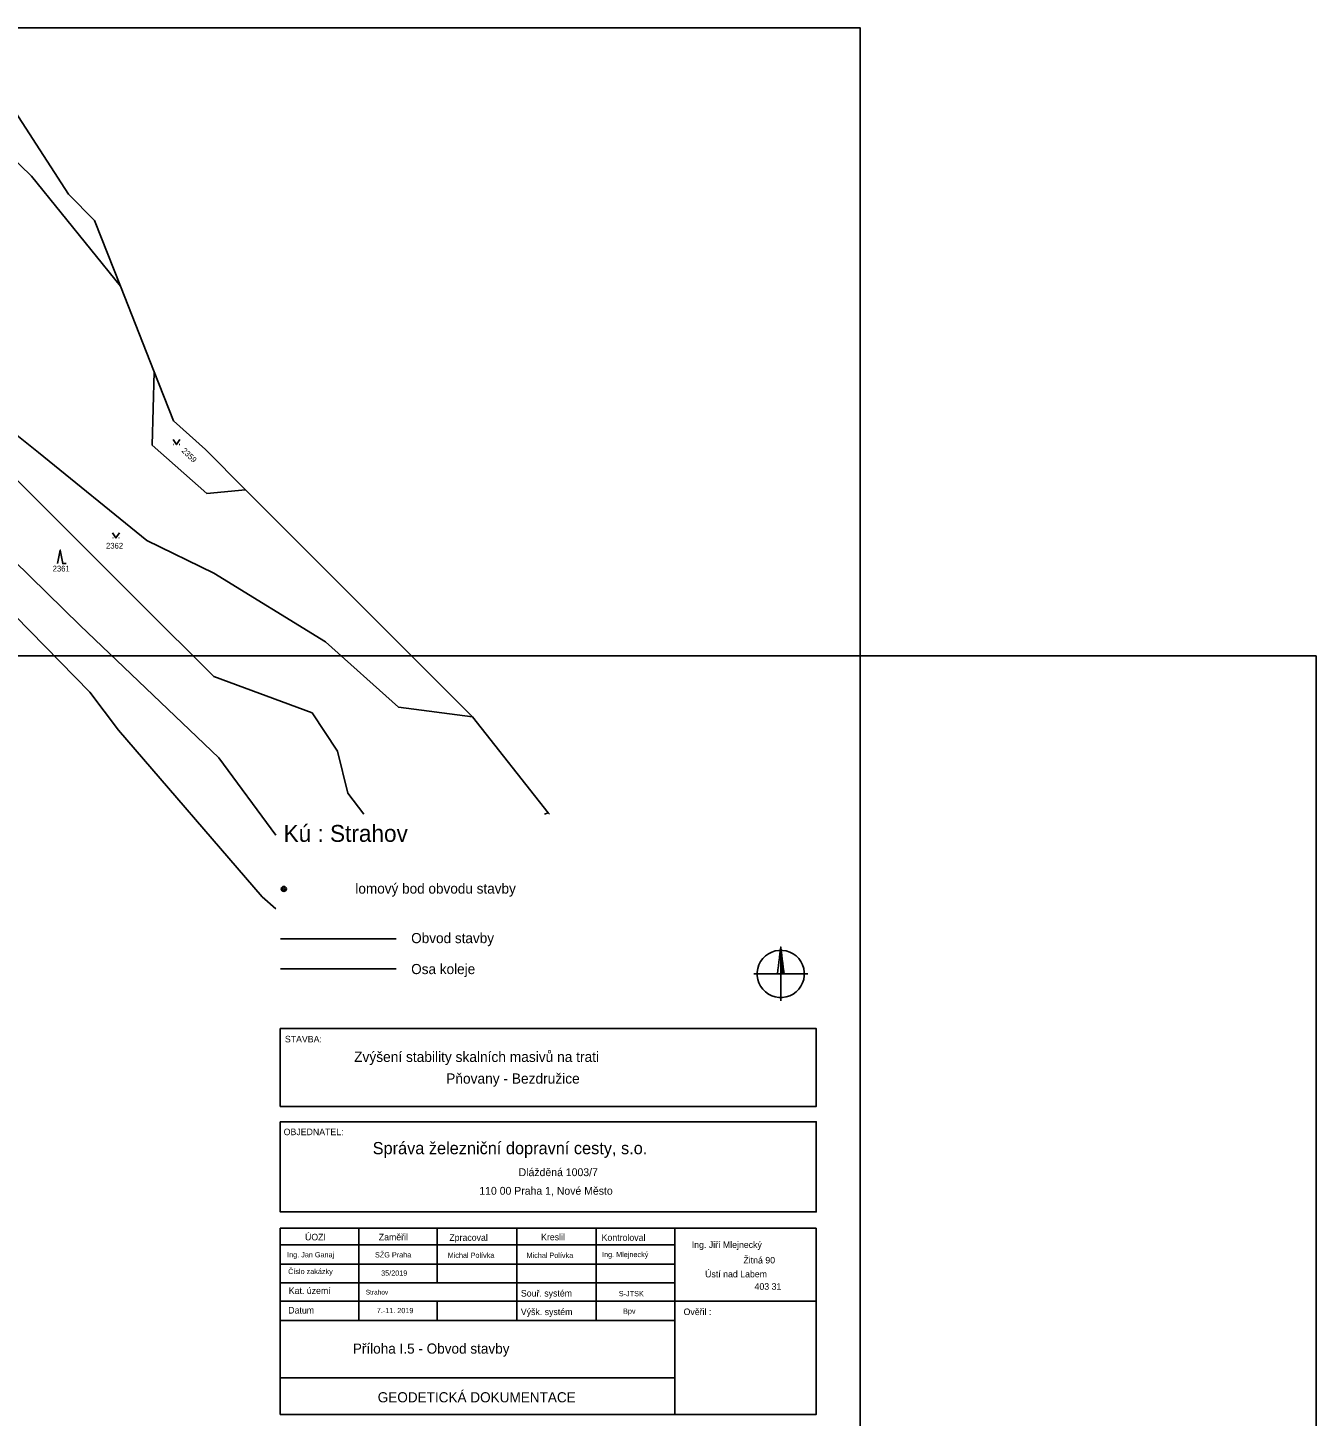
# Model space of a CAD drawing. Extents: x -852001 to -842497, y -1063614 to -1052182.
# Drawn here: x -849131.5 to -848750, y -1053225.1 to -1052814.2 of the extents above; entities that cross this region are included whole.
import ezdxf

# ---------------------------------------------------------------- set-up
doc = ezdxf.new("R2010")
doc.units = 0
for name, color, linetype in [('body', 7, 'Continuous'), ('Default', 7, 'Continuous'), ('KLADY_ZMVM', 7, 'Continuous'), ('KN_HRANICE', 7, 'Continuous'), ('KN_KULTURY', 7, 'Continuous'), ('KN_PARCELY', 7, 'Continuous'), ('LEGENDA', 7, 'Continuous'), ('tabulka', 7, 'Continuous')]:
    doc.layers.add(name, color=color, linetype=linetype)

# ---------------------------------------------------------------- blocks, each defined once
blk = doc.blocks.new('SEVER')
at = {"layer": 'Default'}
for points in [[(5.5, 69.8), (16.3, 68.1), (26.7, 64.7), (36.5, 59.7), (45.4, 53.2), (53.2, 45.4), (59.7, 36.5), (64.7, 26.7), (68.1, 16.3), (69.8, 5.5), (69.8, -5.5), (68.1, -16.3), (64.7, -26.7), (59.7, -36.5), (53.2, -45.4), (45.4, -53.2), (36.5, -59.7), (26.7, -64.7), (16.3, -68.1), (5.5, -69.8), (-5.5, -69.8), (-16.3, -68.1), (-26.7, -64.7), (-36.5, -59.7), (-45.4, -53.2), (-53.2, -45.4), (-59.7, -36.5), (-64.7, -26.7), (-68.1, -16.3), (-69.8, -5.5), (-69.8, 5.5), (-68.1, 16.3), (-64.7, 26.7), (-59.7, 36.5), (-53.2, 45.4), (-45.4, 53.2), (-36.5, 59.7), (-26.7, 64.7), (-16.3, 68.1), (-5.5, 69.8), (5.5, 69.8)], [(-10, 0), (-8.5, 12), (-7, 24), (-5.5, 36), (-4, 48), (-2.5, 60), (-1, 72), (0, 80), (1.5, 68), (3, 56), (4.5, 44), (6, 32), (7.5, 20), (9, 8), (10, 0), (9.2, 0.8), (9.2, 5.6), (8.4, 12), (8.4, 0.8), (7.6, 0.8), (7.6, 13.5), (7.6, 18.4), (6.8, 24.8), (6.8, 12.1), (6.8, 0.8), (6, 0.8), (6, 13.5), (6, 26.2), (6, 31.2), (5.2, 36.8), (5.2, 24.1), (5.2, 11.4), (5.2, 0.8), (4.4, 0.8), (4.4, 13.5), (4.4, 26.2), (4.4, 38.9), (4.4, 43.2), (3.6, 50.4), (3.6, 37.7), (3.6, 25), (3.6, 12.3), (3.6, 0.8), (2.8, 0.8), (2.8, 13.5), (2.8, 26.2), (2.8, 38.9), (2.8, 51.6), (2.8, 56), (2, 63.2), (2, 50.5), (2, 37.8), (2, 25.1), (2, 12.4), (2, 0.8), (1.2, 0.8), (1.2, 13.5), (1.2, 26.2), (1.2, 38.9), (1.2, 51.6), (1.2, 64.3), (1.2, 69.6), (0.4, 76), (0.4, 63.3), (0.4, 50.6), (0.4, 37.9), (0.4, 25.2), (0.4, 12.5), (0.4, 0.8)], [(0, 80), (0, 67.3), (0, 54.6), (0, 41.9), (0, 29.2), (0, 16.5), (0, 3.8), (0, -8.9), (0, -21.6), (0, -34.3), (0, -47), (0, -59.7), (0, -72.4), (0, -80)], [(80, 0), (67.3, 0), (54.6, 0), (41.9, 0), (29.2, 0), (16.5, 0), (3.8, 0), (-8.9, 0), (-21.6, 0), (-34.3, 0), (-47, 0), (-59.7, 0), (-72.4, 0), (-80, 0)]]:
    blk.add_lwpolyline(points, dxfattribs=at)
blk = doc.blocks.new('308')
at = {"layer": 'Default'}
blk.add_lwpolyline([(-0.75, 0), (0, 4), (0.75, 0), (1.75, 0)], dxfattribs=at)
blk = doc.blocks.new('314')
at = {"layer": 'Default'}
for p, q in [((-0.95, 0), (-0.85, 0)), ((0.85, 0), (0.95, 0))]:
    blk.add_line(p, q, dxfattribs=at)
blk.add_lwpolyline([(-1, 1.5), (0, 0), (1, 1.5)], dxfattribs=at)

msp = doc.modelspace()

# ---------------------------------------------------------------- linework, layer by layer
at = {"layer": 'body'}
for radius in [0.75, 0.35]:
    msp.add_circle((-849055.64, -1053069.02), radius, dxfattribs=at)
at = {"layer": 'KLADY_ZMVM'}
for p in [(-849375, -1053000), (-848750, -1053500)]:
    msp.add_line(p, (-848750, -1053000), dxfattribs=at)
at = {"layer": 'KN_HRANICE'}
for p, q in [((-849159.24, -1052830.23), (-849130.37, -1052858.08)), ((-849119.37, -1052863.43), (-849140.56, -1052830.72)), ((-849130.37, -1052858.08), (-849104.04, -1052890.61)), ((-849111.68, -1052871.19), (-849119.37, -1052863.43)), ((-849104.04, -1052890.61), (-849111.68, -1052871.19)), ((-849094.05, -1052915.99), (-849104.04, -1052890.61)), ((-849164.08, -1052911.56), (-849128.24, -1052939.84)), ((-849094.05, -1052915.99), (-849094.67, -1052937.73)), ((-849088.33, -1052930.52), (-849094.05, -1052915.99)), ((-849078.85, -1052939.02), (-849088.33, -1052930.52)), ((-849094.67, -1052937.73), (-849078.47, -1052951.96)), ((-849066.96, -1052950.91), (-849078.85, -1052939.02)), ((-849128.24, -1052939.84), (-849096.23, -1052965.95)), ((-849135.85, -1052946.77), (-849097.92, -1052984.74)), ((-849078.47, -1052951.96), (-849066.96, -1052950.91)), ((-848999.77, -1053018.11), (-849066.96, -1052950.91)), ((-849147.7, -1052960.02), (-849115.97, -1052991.03)), ((-849096.23, -1052965.95), (-849076.36, -1052975.62)), ((-849076.36, -1052975.62), (-849043.32, -1052995.9)), ((-849139.7, -1052983.63), (-849113.12, -1053010.83)), ((-849097.92, -1052984.74), (-849076.36, -1053006.14)), ((-849074.9, -1053030.24), (-849115.97, -1052991.03)), ((-849043.32, -1052995.9), (-849021.72, -1053015.2)), ((-849076.36, -1053006.14), (-849047.3, -1053016.91)), ((-849113.12, -1053010.83), (-849104.61, -1053022.02)), ((-849047.3, -1053016.91), (-849039.79, -1053028.27)), ((-849021.72, -1053015.2), (-848999.77, -1053018.11)), ((-848977.37, -1053046.46), (-848999.77, -1053018.11)), ((-849104.61, -1053022.02), (-849062.09, -1053071.39)), ((-849039.79, -1053028.27), (-849036.74, -1053040.73)), ((-849074.9, -1053030.24), (-849058.01, -1053053.1)), ((-849036.74, -1053040.73), (-849031.95, -1053046.94)), ((-848978.47, -1053046.94), (-848977.37, -1053046.46)), ((-848977.37, -1053046.46), (-848977.03, -1053046.94)), ((-849062.09, -1053071.39), (-849058.01, -1053074.92))]:
    msp.add_line(p, q, dxfattribs=at)
at = {"layer": 'LEGENDA'}
for p, q in [((-849056.58, -1053083.82), (-849022.39, -1053083.82)), ((-849056.58, -1053092.65), (-849022.39, -1053092.65))]:
    msp.add_line(p, q, dxfattribs=at)
msp.add_lwpolyline([(-849479.05, -1053234.18), (-848885.05, -1053234.18), (-848885.05, -1052814.18), (-849479.05, -1052814.18)], close=True, dxfattribs=at)
at = {"layer": 'tabulka'}
for p, q in [((-849056.68, -1053169.42), (-848898.02, -1053169.42)), ((-849033.39, -1053169.42), (-849033.39, -1053196.74)), ((-849010.24, -1053169.42), (-849010.24, -1053185.62)), ((-848986.64, -1053169.42), (-848986.64, -1053196.74)), ((-848963.19, -1053169.42), (-848963.19, -1053196.74)), ((-848939.89, -1053224.55), (-848939.89, -1053169.42)), ((-849056.68, -1053174.33), (-848939.89, -1053174.33)), ((-849056.68, -1053180.04), (-848939.89, -1053180.04)), ((-849056.68, -1053185.62), (-848939.89, -1053185.62)), ((-849056.68, -1053191.04), (-848898.02, -1053191.04)), ((-849010.24, -1053191.04), (-849010.24, -1053196.74)), ((-849056.68, -1053196.74), (-848939.89, -1053196.74)), ((-849056.68, -1053213.73), (-848939.89, -1053213.73))]:
    msp.add_line(p, q, dxfattribs=at)
for points in [[(-849056.68, -1053110.33), (-848898.02, -1053110.33), (-848898.02, -1053133.4), (-849056.68, -1053133.4)], [(-849056.68, -1053137.92), (-848898.02, -1053137.92), (-848898.02, -1053164.61), (-849056.68, -1053164.61)]]:
    msp.add_lwpolyline(points, close=True, dxfattribs=at)
msp.add_lwpolyline([(-848898.02, -1053169.42), (-848898.02, -1053224.55), (-849056.68, -1053224.55), (-849056.68, -1053169.42)], dxfattribs=at)

# ---------------------------------------------------------------- block references
at = {"layer": 'KN_KULTURY'}
for name, p in [('314', (-849087.43, -1052937.53)), ('314', (-849105.33, -1052965.16)), ('308', (-849121.85, -1052972.73))]:
    msp.add_blockref(name, p, dxfattribs=at)
at = {"layer": 'LEGENDA', "xscale": 0.1, "yscale": 0.10000000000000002}
msp.add_blockref('SEVER', (-848908.53, -1053094.18), dxfattribs=at)

# ---------------------------------------------------------------- texts
at = {"layer": 'KN_PARCELY'}
msp.add_text('2359', height=1.7, rotation=315.757, dxfattribs=at).set_placement((-849086.05, -1052939.52))
for s, p in [('2362', (-849108.28, -1052968.31)), ('2361', (-849124.08, -1052975.08))]:
    msp.add_text(s, height=1.7, dxfattribs=at).set_placement(p)
at = {"layer": 'LEGENDA'}
for s, height, p in [('Kú : Strahov', 5, (-849055.72, -1053055.09)), ('lomový bod obvodu stavby', 3, (-849034.46, -1053070.41)), ('Obvod stavby', 3, (-849017.94, -1053085.07)), ('Osa koleje', 3, (-849017.94, -1053094.23)), ('Zvýšení stability skalních masivů na trati', 3.04, (-849034.84, -1053120.23)), ('Pňovany - Bezdružice', 3.04, (-849007.58, -1053126.65))]:
    msp.add_text(s, height=height, dxfattribs=at).set_placement(p)
at = {"layer": 'tabulka'}
for s, height, p in [('STAVBA:', 1.94, (-849055.33, -1053114.44)), ('OBJEDNATEL:', 1.94, (-849055.69, -1053141.9)), ('Správa železniční dopravní cesty, s.o.', 3.61, (-849029.34, -1053147.53)), ('Dlážděná 1003/7', 2.32, (-848986.13, -1053154.02)), ('110 00 Praha 1, Nové Město', 2.32, (-848997.77, -1053159.52)), ('ÚOZI', 1.94, (-849049.37, -1053173.02)), ('Zaměřil', 1.94, (-849027.54, -1053173.02)), ('Zpracoval', 1.94, (-849006.65, -1053173.17)), ('Kreslil', 1.94, (-848979.48, -1053173.02)), ('Kontroloval', 1.94, (-848961.57, -1053173.17)), ('Ing. Jiří Mlejnecký', 1.94, (-848934.88, -1053175.28)), ('Ing. Jan Ganaj', 1.552, (-849054.67, -1053178.05)), ('SŽG Praha', 1.552, (-849028.65, -1053178.08)), ('Michal Polívka', 1.552, (-849007.13, -1053178.2)), ('Michal Polívka', 1.552, (-848983.79, -1053178.24)), ('Ing. Mlejnecký', 1.552, (-848961.43, -1053177.98)), ('Žitná 90', 1.94, (-848919.59, -1053179.86)), ('Číslo zakázky', 1.552, (-849054.37, -1053183)), ('Ústí nad Labem', 1.94, (-848930.92, -1053183.98)), ('35/2019', 1.552, (-849026.84, -1053183.49)), ('403 31', 1.94, (-848916.29, -1053187.64)), ('Kat. území', 1.94, (-849054.18, -1053188.88)), ('Strahov', 1.397, (-849031.4, -1053189.05)), ('Souř. systém', 1.94, (-848985.46, -1053189.65)), ('S-JTSK', 1.552, (-848956.47, -1053189.56)), ('Datum', 1.94, (-849054.33, -1053194.68)), ('7.-11. 2019', 1.552, (-849028.12, -1053194.57)), ('Výšk. systém', 1.94, (-848985.48, -1053195.14)), ('Bpv', 1.552, (-848955.21, -1053194.75)), ('Ověřil :', 1.94, (-848937.3, -1053195.14)), ('Příloha I.5 - Obvod stavby', 3, (-849035.21, -1053206.55)), ('GEODETICKÁ DOKUMENTACE ', 3, (-849027.85, -1053220.96))]:
    msp.add_text(s, height=height, dxfattribs=at).set_placement(p)

doc.saveas('drawing.dxf')
